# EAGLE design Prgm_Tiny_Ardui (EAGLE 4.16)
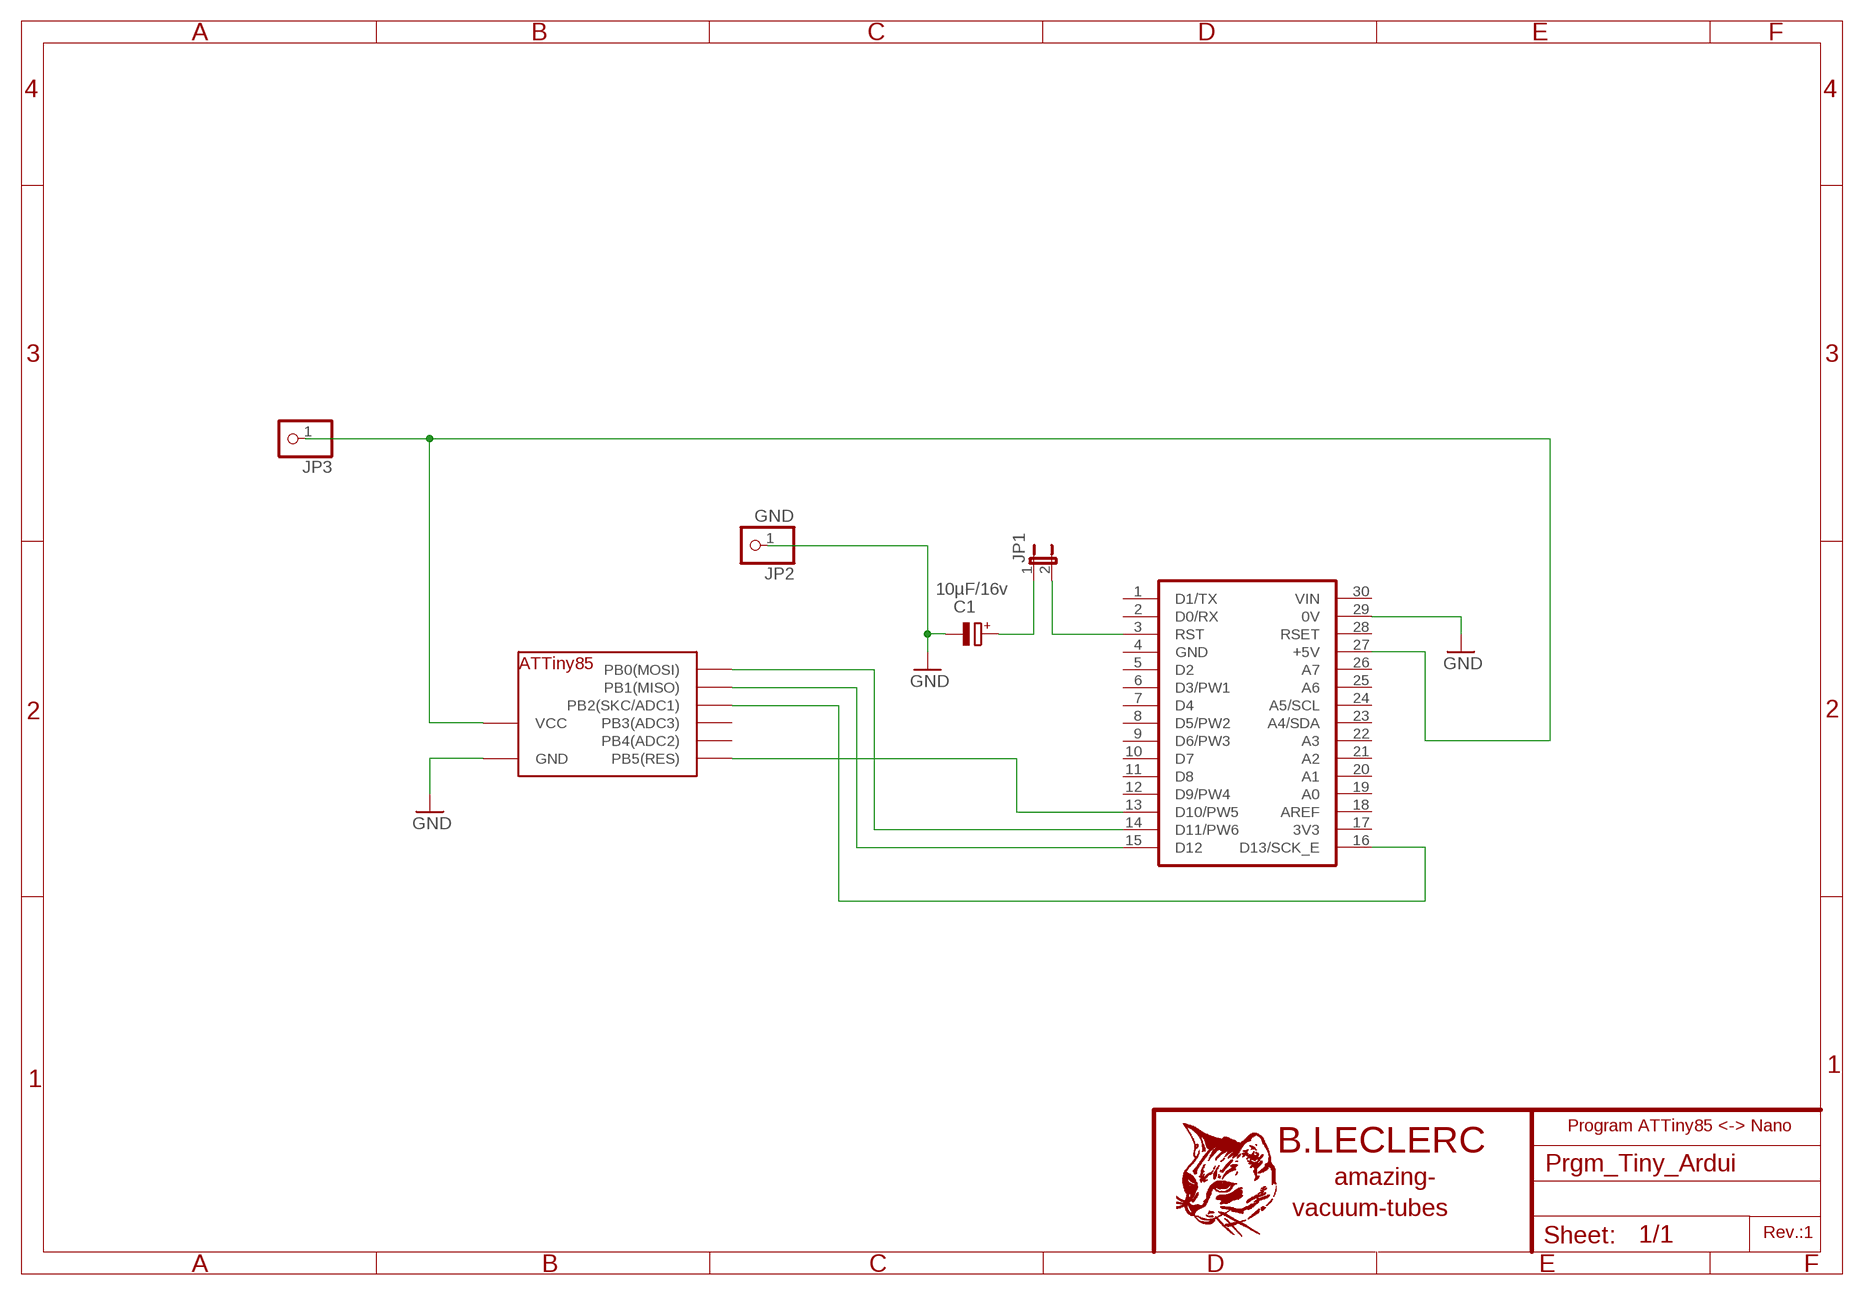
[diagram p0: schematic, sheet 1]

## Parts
C1  10µF/16v  CPOL-EUE2-5  [E2-5]
JP1  JP1E  [JP1]
JP2  GND  PINHD-1X1  [1X01]
JP3  PINHD-1X1  [1X01]
U1  NANO  [NANO]
U$2  ATTINY85  [DIL08]

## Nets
GND: C1.- JP2.1 U1.29(0V) U$2.4(GND)
N$2: C1.+ JP1.1
N$3: JP3.1 U1.27(+5V) U$2.8(VCC)
N$4: U1.14(D11/PW6) U$2.5(PB0(MOSI))
N$5: U1.15(D12) U$2.6(PB1(MISO))
N$6: U1.16(D13/SCK_E) U$2.7(PB2(SKC/ADC1))
N$7: U1.13(D10/PW5) U$2.1(PB5(RES))
N$16: JP1.2 U1.3(RST)
Unconnected: U1.1(D1/TX) U1.2(D0/RX) U1.5(D2) U1.6(D3/PW1) U1.7(D4) U1.8(D5/PW2) U1.9(D6/PW3) U1.10(D7) U1.11(D8) U1.12(D9/PW4) U1.18(AREF) U1.19(A0) U1.20(A1) U1.21(A2) U1.22(A3) U1.23(A4/SDA) U1.24(A5/SCL) U1.25(A6) U1.26(A7) U1.28(RSET) U$2.2(PB3(ADC3)) U$2.3(PB4(ADC2))

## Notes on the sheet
- Program ATTiny85 <-> Nano
- Rev.:1

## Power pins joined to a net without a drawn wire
3V3: U1.17(3V3)
GND: U1.4(GND)
VIN: U1.30(VIN)

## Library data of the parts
C1 = rcl:CPOL-EU: POLARIZED CAPACITOR, European symbol
JP1 = jumper:JP1E: JUMPER
JP2 JP3 = pinhead:PINHD-1X1: PIN HEADER
U1 = Arduino:NANO
U$2 = atmel:ATTINY85

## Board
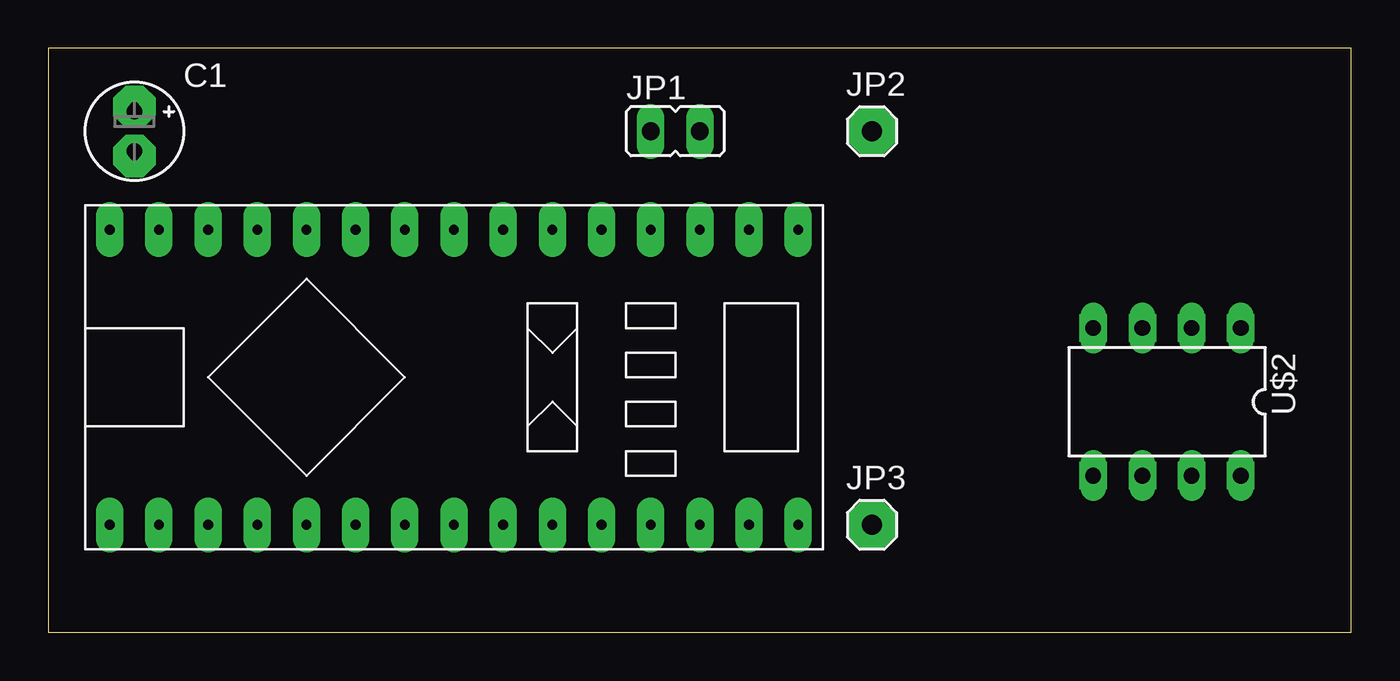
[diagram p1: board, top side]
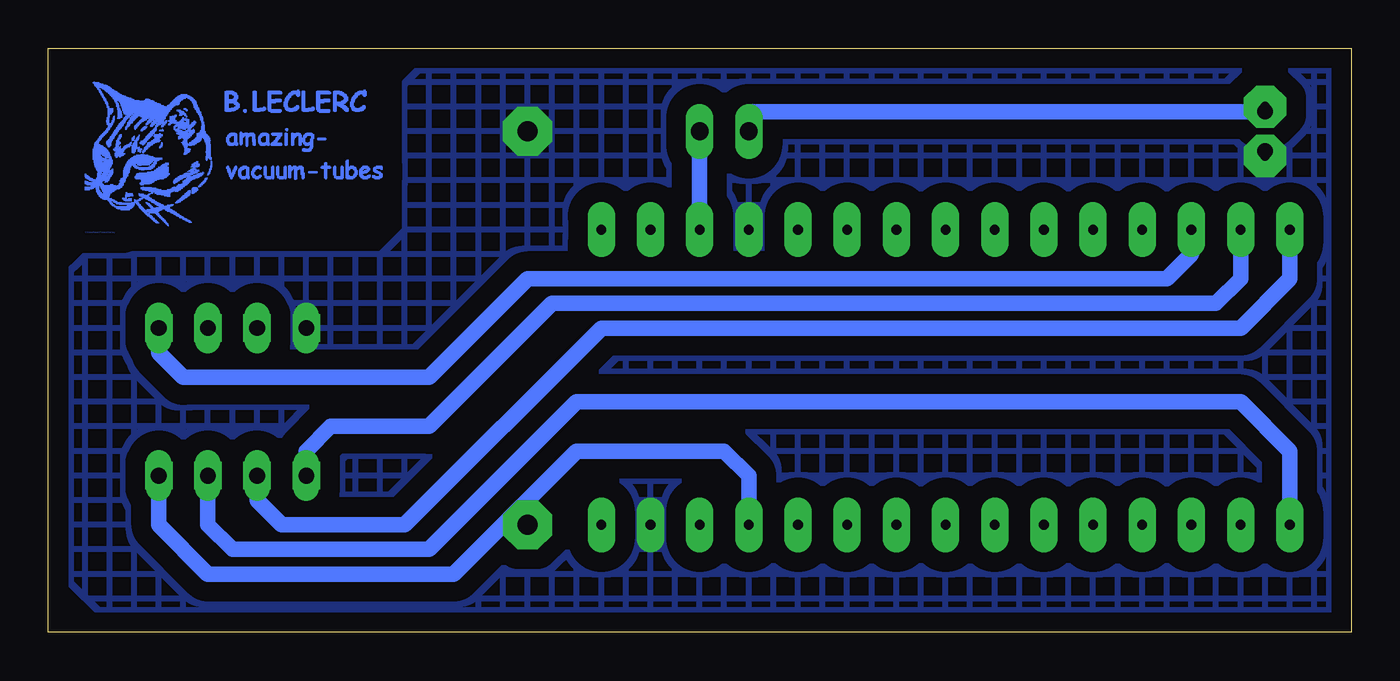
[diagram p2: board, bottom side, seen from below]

Size 67.29 x 30.15 mm. Coordinates in mm from the lower left corner, seen from the top.
Outline: 0,0 67.29,0 67.29,30.15 0,30.15 0,0
Copper layers (1*16): Top 0.035mm / dielectric 1.5mm / Bottom 0.035mm
Design rules "default": minimum track width 10mil, minimum drill 24mil, track to track 8mil, track to pad 8mil, pad to pad 8mil, via to via 8mil, smd to smd 8mil, copper to edge 40mil, drill to drill 8mil, minimum pad ring 10mil, minimum via ring 8mil, stop-mask expansion 4mil, vias tented up to drill 0mil, thermal gap 10mil

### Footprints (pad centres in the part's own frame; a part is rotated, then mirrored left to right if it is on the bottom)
E2-5 = drill 0.813 pad 1.27 round: + -1.016,0 | drill 0.813 pad 1.27 octagon: - 1.016,0
JP1 = drill 0.914 long: 1 0,-1.27; 2 0,1.27
1X01 = drill 1.016 octagon: 1 0,0
NANO = drill 0.5 pad 1.422 long: 1 -7.62,17.78; 2 -7.62,15.24; 3 -7.62,12.7; 4 -7.62,10.16; 5 -7.62,7.62; 6 -7.62,5.08; 7 -7.62,2.54; 8 -7.62,0; 9 -7.62,-2.54; 10 -7.62,-5.08; 11 -7.62,-7.62; 12 -7.62,-10.16; 13 -7.62,-12.7; 14 -7.62,-15.24; 15 -7.62,-17.78; 16 7.62,-17.78; 17 7.62,-15.24; 18 7.62,-12.7; 19 7.62,-10.16; 20 7.62,-7.62; 21 7.62,-5.08; 22 7.62,-2.54; 23 7.62,0; 24 7.62,2.54; 25 7.62,5.08; 26 7.62,7.62; 27 7.62,10.16; 28 7.62,12.7; 29 7.62,15.24; 30 7.62,17.78
DIL08 = drill 0.813 long: 1 -3.81,-3.81; 2 -1.27,-3.81; 3 1.27,-3.81; 4 3.81,-3.81; 5 3.81,3.81; 6 1.27,3.81; 7 -1.27,3.81; 8 -3.81,3.81

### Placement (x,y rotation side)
C1  4.44,25.87 270 top
JP1  32.38,25.87 270 top
JP2  42.54,25.87 0 top
JP3  42.54,5.55 0 top
U1  20.95,13.17 270 top
U$2  57.78,11.9 180 top
U$3  [CHAT]  65.4,20.79 0 bottom

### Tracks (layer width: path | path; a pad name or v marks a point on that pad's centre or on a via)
GND  (via drill 0.5 pad 1.42, 0.5 pad 2.18, 0.5 pad 2.54)
  other vias: 4.44,24.6 42.54,25.87 53.97,15.71
  pour Bottom (isolate 1.016, no thermals, hatched): 0.63,29.68 47.62,29.68 48.89,28.41 48.89,20.79 50.16,19.52 65.4,19.52 66.67,18.25 66.67,3.01 64.13,0.47 0.63,0.47
N$1  (via drill 0.5 pad 1.42)
  other vias: 56.51,15.71
N$2
  Bottom 0.813: C1.+ 31.11,26.89 JP1.1
N$3
  Bottom 0.813: U1.27 31.11,8.09 32.38,9.36 40,9.36 43.81,5.55 | 43.81,5.55 46.35,3.01 59.05,3.01 61.59,5.55 U$2.8 | 43.81,5.55 JP3.1
N$4
  Bottom 0.813: U1.14 5.71,18.25 6.98,16.98 41.27,16.98 47.62,10.63 52.7,10.63 53.97,9.36 U$2.5
N$5
  Bottom 0.813: U1.15 3.17,18.25 5.71,15.71 38.73,15.71 48.89,5.55 55.24,5.55 56.51,6.82 U$2.6
N$6
  Bottom 0.813: U1.16 3.17,9.36 5.71,11.9 40,11.9 47.62,4.28 57.78,4.28 59.05,5.55 U$2.7
N$7
  Bottom 0.813: U$2.1 61.59,14.44 60.32,13.17 47.62,13.17 42.54,18.25 9.52,18.25 8.25,19.52 U1.13
N$8  (via drill 0.5 pad 2.18)
  other vias: 4.44,27.14
N$10  (via drill 0.5 pad 1.42)
  other vias: 53.97,8.09
N$11  (via drill 0.5 pad 1.42)
  other vias: 56.51,8.09
N$12  (via drill 0.5 pad 1.42)
  other vias: 59.05,8.09
N$13  (via drill 0.5 pad 1.42)
  other vias: 61.59,8.09
N$14  (via drill 0.5 pad 1.42)
  other vias: 61.59,15.71
N$15  (via drill 0.5 pad 1.42)
  other vias: 59.05,15.71
N$16
  Bottom 0.813: U1.3 JP1.2
N$17  (via drill 0.5 pad 1.27)
  other vias: 31.11,25.87
N$18  (via drill 0.5 pad 1.27)
  other vias: 33.65,25.87
N$20  (via drill 0.5 pad 2.54)
  other vias: 42.54,5.55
